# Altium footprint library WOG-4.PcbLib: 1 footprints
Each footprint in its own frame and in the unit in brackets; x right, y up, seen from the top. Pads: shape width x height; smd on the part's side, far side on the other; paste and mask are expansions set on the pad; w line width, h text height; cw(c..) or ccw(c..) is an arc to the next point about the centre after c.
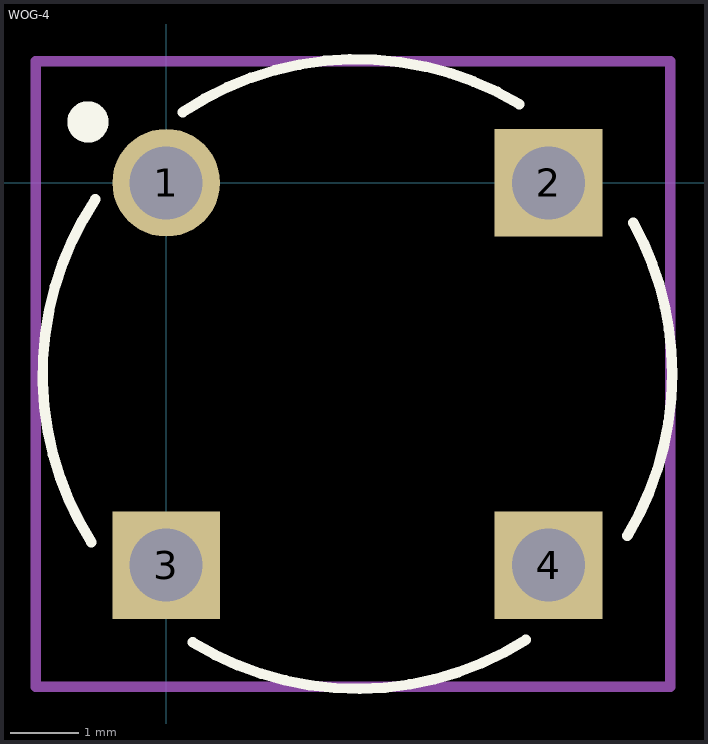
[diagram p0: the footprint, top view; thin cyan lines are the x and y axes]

## WOG-4 [mil]
pads (4):
  round 62 hole 42: 1(0,0)
  rect 62x62 hole 42: 2(220,0) 3(0,-220) 4(220,-220)
Top Overlay:
  circle w13.78: c-45,35 r5
  lines w6: -43,-206.9 cw(c110,-110) -40.69,-9.54 ; 9.54,40.69 cw(c110,-110) 203.18,45.29 ; 15.36,-264.41 ccw(c110,-110) 206.9,-263 ; 265.29,-203.18 ccw(c110,-110) 291.1,-110 ccw(c110,-110) 268.79,-22.92
Mechanical 15:
  lines w6: -75,-290 -75,70 290,70 290,-290 -75,-290
3D body "WOG-4.STEP": height 220.47, standoff -137.8, extent -73.07,-293.07 293.07,73.07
